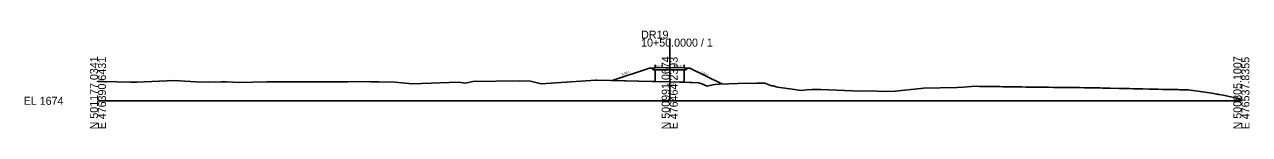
# Model space of a CAD drawing. Extents: x 79370 to 79799, y -95930 to -94349.
# Drawn here: x 79370.3 to 79798.8, y -95430.2 to -95395.9 of the extents above; entities that cross this region are included whole.
import ezdxf

# ---------------------------------------------------------------- set-up
doc = ezdxf.new("R2010")
doc.units = 0
for name, color, linetype in [('Exist Cross Section Cell', 7, 'Continuous'), ('Exist XS Center Line Elevation Label', 7, 'Continuous'), ('Exist XS Ground Line', 7, 'Continuous'), ('Prop XS Earthwork Shape', 7, 'Continuous'), ('Prop XS EOT Tick Mark', 7, 'Continuous'), ('Prop XS Finish Grade', 7, 'Continuous'), ('Prop XS Finish Grade Earthwork', 7, 'Continuous'), ('Prop XS Finish Grade Pavement', 7, 'Continuous'), ('Prop XS Pvmt Edge Slope', 7, 'Continuous'), ('Prop XS SE Text', 7, 'Continuous'), ('Prop XS Shoulder Borrow Shape', 7, 'Continuous'), ('Prop XS Side Slope Text', 7, 'Continuous'), ('Prop XS Subgrade Earthwork', 7, 'Continuous'), ('Scratch_Level_6', 7, 'Continuous')]:
    doc.layers.add(name, color=color, linetype=linetype)

msp = doc.modelspace()

# ---------------------------------------------------------------- linework, layer by layer
at = {"layer": 'Exist Cross Section Cell'}
for p, q in [((79596.01, -95420.51), (79596.01, -95398.72)), ((79396.01, -95420.51), (79596.01, -95420.51)), ((79596.01, -95420.51), (79796.01, -95420.51))]:
    msp.add_line(p, q, dxfattribs=at)
at = {"layer": 'Exist XS Ground Line'}
msp.add_lwpolyline([(79396.01, -95413.79), (79397.98, -95413.75), (79407.37, -95413.95), (79408.35, -95413.95), (79408.73, -95413.96), (79409.63, -95413.97), (79422.67, -95413.36), (79430.26, -95413.89), (79434.55, -95413.98), (79439.17, -95413.83), (79441.01, -95413.9), (79445.23, -95414.09), (79455.13, -95413.81), (79463.2, -95413.88), (79465.36, -95413.82), (79483.44, -95413.9), (79487.33, -95413.73), (79491.45, -95413.81), (79494.22, -95413.82), (79500.04, -95413.94), (79505.92, -95414.6), (79522.19, -95413.92), (79524.62, -95414.32), (79527.11, -95413.76), (79543.34, -95413.45), (79547.34, -95413.67), (79551.08, -95414.61), (79570.19, -95413.24), (79570.49, -95413.25), (79589.84, -95413.74), (79596.01, -95413.89), (79603.05, -95414.07), (79603.38, -95414.08), (79603.88, -95414.09), (79606.27, -95414.16), (79606.61, -95414.3), (79607.3, -95414.6), (79609.11, -95415.4), (79611.01, -95414.86), (79611.91, -95414.75), (79613.28, -95414.63), (79616.65, -95414.54), (79619.85, -95414.47), (79626.48, -95414.32), (79627, -95414.3), (79627.39, -95414.29), (79628.61, -95414.32), (79629.3, -95414.34), (79631.68, -95415.26), (79632.28, -95415.26), (79633.23, -95415.6), (79633.74, -95415.67), (79638.85, -95416.44), (79642, -95416.91), (79644.04, -95416.69), (79645.7, -95416.51), (79646.42, -95416.53), (79648.92, -95416.5), (79662.82, -95417.17), (79666.94, -95417), (79670.28, -95417.28), (79674.9, -95417.14), (79683.91, -95416.14), (79684.78, -95416.05), (79696.61, -95415.81), (79698.68, -95415.7), (79701.56, -95415.53), (79703.26, -95415.43), (79704.39, -95415.45), (79705.03, -95415.46), (79706.26, -95415.48), (79707.31, -95415.49), (79708.79, -95415.5), (79709.37, -95415.51), (79709.97, -95415.52), (79710.79, -95415.53), (79711.39, -95415.54), (79712.56, -95415.56), (79714.58, -95415.59), (79715.28, -95415.6), (79717.22, -95415.63), (79718.03, -95415.64), (79718.41, -95415.64), (79719.26, -95415.65), (79720.62, -95415.67), (79721.46, -95415.68), (79723.32, -95415.7), (79726.14, -95415.74), (79727.9, -95415.77), (79728.7, -95415.78), (79730.35, -95415.8), (79731.35, -95415.81), (79732.81, -95415.83), (79734.18, -95415.84), (79735.61, -95415.85), (79736.79, -95415.86), (79737.2, -95415.87), (79739.4, -95415.88), (79741.07, -95415.9), (79741.9, -95415.92), (79742.24, -95415.93), (79744.18, -95415.96), (79744.9, -95415.97), (79745.34, -95415.98), (79746.47, -95416.01), (79747.47, -95416.03), (79749.18, -95416.07), (79750.16, -95416.09), (79753.29, -95416.15), (79755.64, -95416.2), (79756.86, -95416.24), (79758.23, -95416.27), (79760.01, -95416.31), (79760.9, -95416.33), (79761.52, -95416.35), (79763.72, -95416.39), (79766.89, -95416.46), (79768.41, -95416.49), (79769, -95416.5), (79770.24, -95416.52), (79770.99, -95416.53), (79771.54, -95416.54), (79772.32, -95416.56), (79772.85, -95416.57), (79773.9, -95416.59), (79774.46, -95416.6), (79776.43, -95416.64), (79776.9, -95416.65), (79777.43, -95416.65), (79784.02, -95417.64), (79786.33, -95417.99), (79787.28, -95418.13), (79787.81, -95418.21), (79788.13, -95418.26), (79789.61, -95418.48), (79796.01, -95419.96)], dxfattribs=at)
at = {"layer": 'Prop XS Earthwork Shape'}
for points in [[(79588.9, -95409.09), (79575.92, -95413.39), (79589.84, -95413.74), (79590.91, -95413.76), (79590.91, -95409.6), (79590.23, -95409.61), (79589.64, -95409.03)], [(79575.92, -95413.39), (79589.84, -95413.74), (79596.01, -95413.89), (79603.05, -95414.07), (79603.38, -95414.08), (79603.88, -95414.09), (79606.27, -95414.16), (79606.61, -95414.3), (79607.3, -95414.6), (79609.11, -95415.4), (79611.01, -95414.86), (79611.91, -95414.75), (79613.28, -95414.63), (79614.24, -95414.61), (79603.12, -95409.09), (79602.37, -95409.03), (79601.79, -95409.61), (79601.11, -95409.6), (79590.91, -95409.6), (79590.23, -95409.61), (79589.64, -95409.03), (79588.9, -95409.09)], [(79601.11, -95409.6), (79601.79, -95409.61), (79602.37, -95409.03), (79603.12, -95409.09), (79614.24, -95414.61), (79613.28, -95414.63), (79611.91, -95414.75), (79611.01, -95414.86), (79609.11, -95415.4), (79607.3, -95414.6), (79606.61, -95414.3), (79606.27, -95414.16), (79603.88, -95414.09), (79603.38, -95414.08), (79603.05, -95414.07), (79601.11, -95414.02)]]:
    msp.add_lwpolyline(points, close=True, dxfattribs=at)
at = {"layer": 'Prop XS EOT Tick Mark'}
for p, q in [((79590.91, -95408.93), (79590.91, -95407.93)), ((79601.11, -95408.93), (79601.11, -95407.93))]:
    msp.add_line(p, q, dxfattribs=at)
at = {"layer": 'Prop XS Finish Grade'}
for p, q in [((79590.91, -95408.93), (79589.64, -95409.03)), ((79601.11, -95408.93), (79602.37, -95409.03))]:
    msp.add_line(p, q, dxfattribs=at)
at = {"layer": 'Prop XS Finish Grade Earthwork'}
for p, q in [((79588.9, -95409.09), (79575.92, -95413.39)), ((79589.64, -95409.03), (79588.9, -95409.09)), ((79602.37, -95409.03), (79603.12, -95409.09)), ((79603.12, -95409.09), (79614.24, -95414.61))]:
    msp.add_line(p, q, dxfattribs=at)
at = {"layer": 'Prop XS Finish Grade Pavement'}
for p, q in [((79590.91, -95408.93), (79596.01, -95408.83)), ((79596.01, -95408.83), (79601.11, -95408.93))]:
    msp.add_line(p, q, dxfattribs=at)
at = {"layer": 'Prop XS Pvmt Edge Slope'}
for p, q in [((79590.91, -95408.93), (79590.23, -95409.61)), ((79601.11, -95408.93), (79601.79, -95409.61))]:
    msp.add_line(p, q, dxfattribs=at)
at = {"layer": 'Prop XS Shoulder Borrow Shape'}
for points in [[(79590.91, -95408.93), (79590.23, -95409.61), (79589.64, -95409.03)], [(79601.79, -95409.61), (79602.37, -95409.03), (79601.11, -95408.93)]]:
    msp.add_lwpolyline(points, close=True, dxfattribs=at)
at = {"layer": 'Prop XS Subgrade Earthwork'}
for p, q in [((79590.23, -95409.61), (79589.64, -95409.03)), ((79590.91, -95409.6), (79590.23, -95409.61)), ((79601.11, -95409.6), (79590.91, -95409.6)), ((79601.11, -95409.6), (79601.79, -95409.61)), ((79601.79, -95409.61), (79602.37, -95409.03))]:
    msp.add_line(p, q, dxfattribs=at)
at = {"layer": 'Scratch_Level_6'}
msp.add_line((79590.91, -95413.76), (79601.11, -95414.02), dxfattribs=at)

# ---------------------------------------------------------------- texts
at = {"layer": 'Exist Cross Section Cell'}
for s, p in [('10+50.0000 / 1', (79586.01, -95401.52)), ('DR19', (79586.01, -95398.72)), ('EL 1674', (79370.01, -95421.91))]:
    msp.add_text(s, height=2.8, dxfattribs=at).set_placement(p)
for s, p in [('N 501177.0341', (79396.01, -95430.51)), ('E 476390.6431', (79398.81, -95430.51)), ('N 500991.0674', (79596.01, -95430.51)), ('E 476464.2393', (79598.81, -95430.51)), ('N 500805.1007', (79796.01, -95430.51)), ('E 476537.8355', (79798.81, -95430.51))]:
    msp.add_text(s, height=2.8, rotation=90, dxfattribs=at).set_placement(p)
at = {"layer": 'Exist XS Center Line Elevation Label'}
msp.add_text('1680.61', height=0.75, dxfattribs=at).set_placement((79594.43, -95415.14))
at = {"layer": 'Prop XS SE Text'}
for rotation, p in [(1.1458, (79591.17, -95408.81)), (358.8542, (79597.81, -95408.74))]:
    msp.add_text('0.020', height=0.75, rotation=rotation, dxfattribs=at).set_placement(p)
at = {"layer": 'Prop XS Side Slope Text'}
for s, rotation, p in [('3.02:1', 18.3301, (79579.36, -95411.6)), ('2.02:1', 333.6066, (79606.86, -95410.74))]:
    msp.add_text(s, height=0.75, rotation=rotation, dxfattribs=at).set_placement(p)

doc.saveas('drawing.dxf')
